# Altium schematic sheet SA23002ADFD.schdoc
size 127 x 101 mm
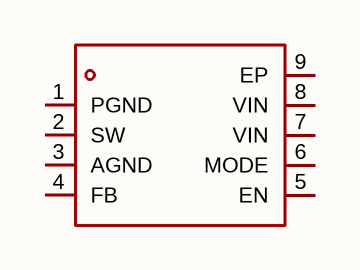
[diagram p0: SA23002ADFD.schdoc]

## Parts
U?  sa23002adfd  [DFN-8_L2.0-W2.0-P0.50-BL-EP1.6_1]  (value not drawn)

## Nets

Not connected (* = marked no-connect by the designer): U? 1(PGND) 2(SW) 3(AGND) 4(FB) 5(EN) 6(MODE) 7(VIN) 8(VIN) 9(EP)

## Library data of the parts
U? = sa23002adfd: 功能类型:降压型;工作电压:2.8V~5.5V;输出电压:600mV~5.5V;输出电流:2A;输出类型:可调;; Manufacturer: Silergy(矽力杰); AddInBom: yes; ModelId: 002e125e8db14b4483f502fafa80fba1; ModelTransform: 79.134,79.527,0,0,0,0,0,0,0; Function: 降压型; Output Current: 2A; Frequency - Switching: 2MHz~2.7MHz; Synchronous Rectifier: 是; Number of Outputs: 1; Topology: 降压式; Quiescent Current: 22uA; Switch tube (built-in/external): 内置; Output Type: 可调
